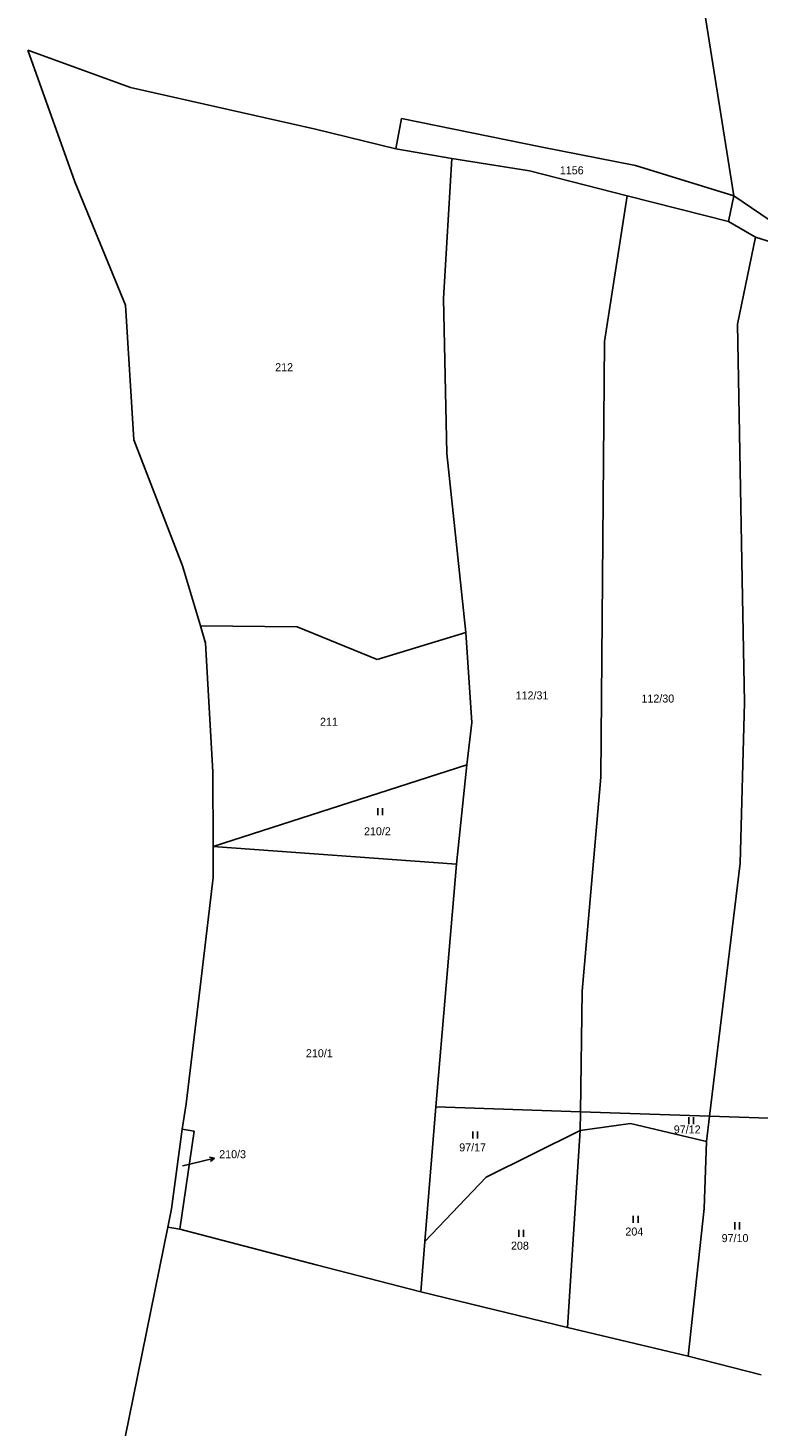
# Model space of a CAD drawing. Extents: x -794142 to -791199, y -1109267 to -1105626.
# Drawn here: x -794094.7 to -793939.7, y -1108029.2 to -1107732.2 of the extents above; entities that cross this region are included whole.
import ezdxf

# ---------------------------------------------------------------- set-up
doc = ezdxf.new("R2010")
doc.units = 0
for name, color, linetype in [('Komunikace', 7, 'Continuous'), ('Vrstva 1', 7, 'Continuous'), ('Vrstva 14', 7, 'Continuous'), ('Vrstva 16', 7, 'Continuous'), ('Vrstva 23', 7, 'Continuous'), ('Vrstva 4', 7, 'Continuous')]:
    doc.layers.add(name, color=color, linetype=linetype)

msp = doc.modelspace()

# ---------------------------------------------------------------- linework, layer by layer
at = {"layer": 'Komunikace'}
msp.add_line((-794061.82, -1107973.91), (-794058.03, -1107972.99), dxfattribs=at)
at = {"layer": 'Vrstva 1'}
for p, q in [((-794016.6, -1107757.88), (-794004.73, -1107759.96)), ((-794004.73, -1107759.96), (-794006.51, -1107789.7)), ((-794004.73, -1107759.96), (-793988.24, -1107762.55)), ((-793988.24, -1107762.55), (-793967.47, -1107767.84)), ((-793967.47, -1107767.84), (-793972.3, -1107798.78)), ((-793967.47, -1107767.84), (-793945.92, -1107773.34)), ((-793944.79, -1107767.86), (-793945.92, -1107773.34)), ((-793944.79, -1107767.86), (-793935.3, -1107774.31)), ((-793940.21, -1107776.65), (-793945.92, -1107773.34)), ((-793940.21, -1107776.65), (-793944.02, -1107795.16)), ((-793940.21, -1107776.65), (-793926.46, -1107780.93)), ((-794006.51, -1107789.7), (-794005.75, -1107822.6)), ((-793944.02, -1107795.16), (-793943.03, -1107849.34)), ((-793972.3, -1107798.78), (-793973.09, -1107891.33)), ((-794005.75, -1107822.6), (-794001.72, -1107860.63)), ((-793943.03, -1107849.34), (-793942.56, -1107875.48)), ((-794037.58, -1107859.4), (-794058.1, -1107859.21)), ((-794020.54, -1107866.37), (-794037.58, -1107859.4)), ((-794001.72, -1107860.63), (-794020.54, -1107866.37)), ((-794001.72, -1107860.63), (-794000.43, -1107879.7)), ((-793942.56, -1107875.48), (-793943.5, -1107909.58)), ((-794000.43, -1107879.7), (-794001.52, -1107888.72)), ((-794055.43, -1107906.09), (-794001.52, -1107888.72)), ((-794001.52, -1107888.72), (-794003.75, -1107909.81)), ((-793973.09, -1107891.33), (-793977, -1107936.81)), ((-794003.75, -1107909.81), (-794055.43, -1107906.09)), ((-794008.13, -1107961.36), (-794003.75, -1107909.81)), ((-793943.5, -1107909.58), (-793949.96, -1107963.33)), ((-793977, -1107936.81), (-793977.4, -1107962.4)), ((-794010.42, -1107989.95), (-794008.13, -1107961.36)), ((-794008.13, -1107961.36), (-793977.4, -1107962.4)), ((-793977.4, -1107962.4), (-793977.43, -1107966.38)), ((-793977.4, -1107962.4), (-793949.96, -1107963.33)), ((-793949.96, -1107963.33), (-793950.61, -1107968.76)), ((-793949.96, -1107963.33), (-793933.23, -1107963.9)), ((-794059.46, -1107966.53), (-794062.47, -1107987.38)), ((-794059.46, -1107966.53), (-794061.96, -1107966.12)), ((-793997.45, -1107976.33), (-793977.43, -1107966.38)), ((-793977.43, -1107966.38), (-793980.17, -1108008.22)), ((-793977.43, -1107966.38), (-793966.75, -1107964.92)), ((-793966.75, -1107964.92), (-793950.61, -1107968.76)), ((-793950.61, -1107968.76), (-793951.15, -1107982.99)), ((-794010.42, -1107989.95), (-793997.45, -1107976.33)), ((-793951.15, -1107982.99), (-793954.49, -1108014.35)), ((-794062.47, -1107987.38), (-794065.03, -1107986.9)), ((-794062.47, -1107987.38), (-794033.55, -1107994.96)), ((-794011.28, -1108000.68), (-794010.42, -1107989.95)), ((-794033.55, -1107994.96), (-794011.28, -1108000.68)), ((-794011.28, -1108000.68), (-793980.17, -1108008.22)), ((-793980.17, -1108008.22), (-793954.49, -1108014.35)), ((-793954.49, -1108014.35), (-793939.04, -1108018.26))]:
    msp.add_line(p, q, dxfattribs=at)
at = {"layer": 'Vrstva 16'}
for p, q in [((-794058.03, -1107972.99), (-794055.114, -1107972.281)), ((-794055.114, -1107972.281), (-794056.204, -1107972.032)), ((-794055.114, -1107972.281), (-794055.968, -1107973.003))]:
    msp.add_line(p, q, dxfattribs=at)
at = {"layer": 'Vrstva 23'}
for p, q in [((-794020.43, -1107899.41), (-794020.43, -1107897.91)), ((-794019.43, -1107897.91), (-794019.43, -1107899.41)), ((-793954.39, -1107965.08), (-793954.39, -1107963.58)), ((-793953.39, -1107963.58), (-793953.39, -1107965.08)), ((-794000.28, -1107968.13), (-794000.28, -1107966.63)), ((-793999.28, -1107966.63), (-793999.28, -1107968.13)), ((-793966.17, -1107986.01), (-793966.17, -1107984.51)), ((-793965.17, -1107984.51), (-793965.17, -1107986.01)), ((-793944.6, -1107987.4), (-793944.6, -1107985.9)), ((-793943.6, -1107985.9), (-793943.6, -1107987.4)), ((-793990.46, -1107989.01), (-793990.46, -1107987.51)), ((-793989.46, -1107987.51), (-793989.46, -1107989.01))]:
    msp.add_line(p, q, dxfattribs=at)
at = {"layer": 'Vrstva 4'}
for p, q in [((-793952.73, -1107718.05), (-793944.79, -1107767.86)), ((-794094.73, -1107736.92), (-794072.95, -1107744.86)), ((-794094.73, -1107736.92), (-794084.77, -1107764.88)), ((-794072.95, -1107744.86), (-794033.65, -1107753.73)), ((-794016.6, -1107757.88), (-794015.39, -1107751.42)), ((-794015.39, -1107751.42), (-793985.54, -1107757.52)), ((-794033.65, -1107753.73), (-794016.6, -1107757.88)), ((-793985.54, -1107757.52), (-793965.68, -1107761.41)), ((-793965.68, -1107761.41), (-793944.79, -1107767.86)), ((-794084.77, -1107764.88), (-794074.02, -1107791.1)), ((-794074.02, -1107791.1), (-794072.24, -1107819.7)), ((-794072.24, -1107819.7), (-794061.93, -1107846.48)), ((-794061.93, -1107846.48), (-794058.1, -1107859.21)), ((-794058.1, -1107859.21), (-794057, -1107862.86)), ((-794057, -1107862.86), (-794055.44, -1107890.22)), ((-794055.43, -1107906.09), (-794055.44, -1107890.22)), ((-794055.42, -1107912.68), (-794055.43, -1107906.09)), ((-794058.17, -1107935.92), (-794055.42, -1107912.68)), ((-794061.11, -1107960.74), (-794058.17, -1107935.92)), ((-794061.96, -1107966.12), (-794061.11, -1107960.74)), ((-794064.25, -1107983.03), (-794061.96, -1107966.12)), ((-794065.03, -1107986.9), (-794064.25, -1107983.03)), ((-794074.16, -1108031.9), (-794065.03, -1107986.9))]:
    msp.add_line(p, q, dxfattribs=at)

# ---------------------------------------------------------------- texts
at = {"layer": 'Vrstva 14'}
for s, height, p in [('1156', 1.7, (-793981.769, -1107763.29)), ('212', 1.7, (-794042.22, -1107805.12)), ('112/31', 1.7, (-793991.159, -1107874.83)), ('112/30', 1.7, (-793964.435, -1107875.5)), ('211', 1.7, (-794032.713, -1107880.43)), ('210/2', 1.7, (-794023.362, -1107903.69)), ('210/1', 1.7, (-794035.695, -1107950.83)), ('97/12', 1.7, (-793957.57, -1107967.02)), ('97/17', 1.7, (-794003.136, -1107970.83)), ('210/3', 0.1, (-794062.011, -1107973.91)), ('204', 1.7, (-793967.852, -1107988.71)), ('208', 1.7, (-793992.146, -1107991.71)), ('97/10', 1.7, (-793947.409, -1107990.1))]:
    msp.add_text(s, height=height, dxfattribs=at).set_placement(p)
at = {"layer": 'Vrstva 16'}
msp.add_text('210/3', height=1.7, dxfattribs=at).set_placement((-794054.11, -1107972.28))

doc.saveas('drawing.dxf')
